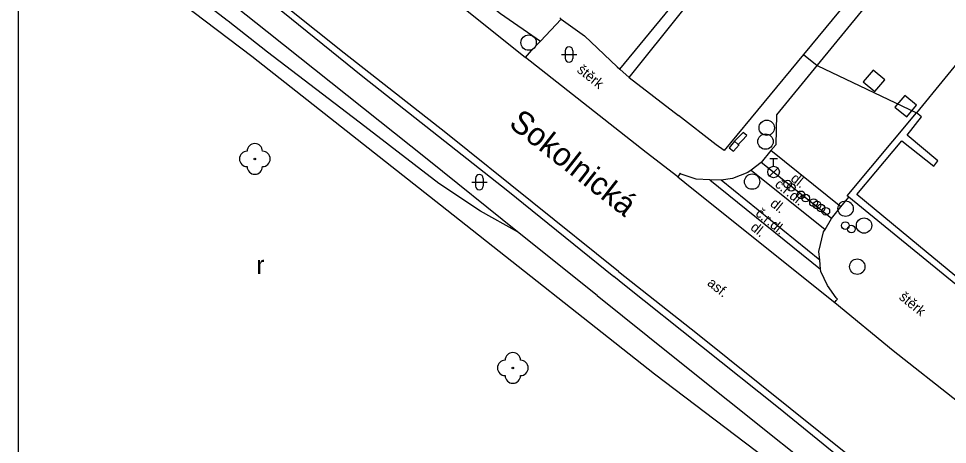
# Model space of a CAD drawing. Extents: x -594386 to -594050, y -1167541 to -1167175.
# Drawn here: x -594386.4 to -594325.8, y -1167256.2 to -1167228.4 of the extents above; entities that cross this region are included whole.
import ezdxf

# ---------------------------------------------------------------- set-up
doc = ezdxf.new("R2010")
doc.units = 0
for name, color, linetype in [('Level 14', 7, 'Continuous'), ('Level 22', 7, 'Continuous'), ('Level 24', 7, 'Continuous'), ('Level 26', 7, 'Continuous'), ('Level 27', 7, 'Continuous'), ('Level 28', 7, 'Continuous'), ('Level 36', 7, 'Continuous'), ('Vrstva 10', 7, 'Continuous'), ('Vrstva 11', 7, 'Continuous'), ('Vrstva 23', 7, 'Continuous'), ('Vrstva 40', 7, 'Continuous'), ('Vrstva 50', 7, 'Continuous'), ('Vrstva 63', 7, 'Continuous'), ('Vrstva 7', 7, 'Continuous'), ('Vrstva 8', 7, 'Continuous')]:
    doc.layers.add(name, color=color, linetype=linetype)

msp = doc.modelspace()

# ---------------------------------------------------------------- linework, layer by layer
at = {"layer": 'Level 14'}
for points in [[(-594372.76, -1167228.57), (-594380.18, -1167222.84), (-594382.36, -1167221.16), (-594386.36, -1167218.111)], [(-594353.85, -1167242.33), (-594359.75, -1167237.6), (-594370.16, -1167229.3), (-594373.63, -1167226.53)], [(-594353.85, -1167242.33), (-594356.26, -1167241), (-594358.99, -1167239.18), (-594363.81, -1167235.48), (-594370.15, -1167230.62), (-594372.71, -1167228.6), (-594372.76, -1167228.57)], [(-594348.66, -1167246.49), (-594353.85, -1167242.33)], [(-594348.66, -1167246.49), (-594343.72, -1167250.47), (-594329.57, -1167261.75), (-594315.59, -1167273.12), (-594302.08, -1167284.23), (-594289.99, -1167294.24), (-594283.19, -1167300.21), (-594279.82, -1167303.19), (-594277.77, -1167305.01), (-594276.73, -1167306.15)]]:
    msp.add_lwpolyline(points, dxfattribs=at)
at = {"layer": 'Level 22'}
for centre in [(-594370.97, -1167237.59), (-594354.16, -1167251.21)]:
    msp.add_circle(centre, 0.05, dxfattribs=at)
for centre, start, end in [((-594371.47, -1167237.59), 90, 270), ((-594370.97, -1167237.09), 0, 180), ((-594370.47, -1167237.59), 270, 90), ((-594370.97, -1167238.09), 180, 0), ((-594354.16, -1167250.71), 0, 180), ((-594354.66, -1167251.21), 90, 270), ((-594353.66, -1167251.21), 270, 90), ((-594354.16, -1167251.71), 180, 0)]:
    msp.add_arc(centre, 0.5, start, end, dxfattribs=at)
at = {"layer": 'Level 24'}
for points in [[(-594339.48, -1167236.64), (-594339.23, -1167236.38), (-594338.92, -1167236.06), (-594339.15, -1167235.87), (-594339.72, -1167236.44)], [(-594339.72, -1167236.44), (-594340.06, -1167236.87), (-594339.78, -1167237.09), (-594339.61, -1167236.89), (-594339.42, -1167236.68), (-594339.48, -1167236.64)], [(-594339.48, -1167236.64), (-594339.72, -1167236.44)]]:
    msp.add_lwpolyline(points, dxfattribs=at)
at = {"layer": 'Level 26'}
for points in [[(-594330.694, -1167231.796), (-594331.334, -1167232.564), (-594330.566, -1167233.204), (-594329.926, -1167232.436)], [(-594328.624, -1167233.446), (-594329.264, -1167234.214), (-594328.496, -1167234.854), (-594327.856, -1167234.086)]]:
    msp.add_lwpolyline(points, close=True, dxfattribs=at)
at = {"layer": 'Level 27'}
for centre in [(-594353.13, -1167230.01), (-594337.62, -1167235.56), (-594337.7, -1167236.46), (-594338.57, -1167239.07), (-594332.48, -1167240.83), (-594331.28, -1167241.93), (-594331.72, -1167244.61)]:
    msp.add_circle(centre, 0.5, dxfattribs=at)
at = {"layer": 'Level 28'}
for p, q in [((-594337.42, -1167237.565), (-594336.92, -1167237.565)), ((-594337.17, -1167238.065), (-594337.17, -1167237.565)), ((-594337.428, -1167238.712), (-594336.898, -1167238.182))]:
    msp.add_line(p, q, dxfattribs=at)
for centre, radius in [((-594337.17, -1167238.44), 0.375), ((-594336.26, -1167239.23), 0.25), ((-594336.02, -1167239.44), 0.25), ((-594335.38, -1167239.93), 0.25), ((-594335.08, -1167240.14), 0.25), ((-594334.57, -1167240.44), 0.25), ((-594334.34, -1167240.59), 0.25), ((-594334.08, -1167240.79), 0.25), ((-594333.77, -1167241), 0.25), ((-594332.5, -1167241.93), 0.25), ((-594332.1, -1167242.16), 0.25)]:
    msp.add_circle(centre, radius, dxfattribs=at)
at = {"layer": 'Level 36'}
for p, q in [((-594350.996, -1167230.786), (-594349.996, -1167230.786)), ((-594350.746, -1167230.536), (-594350.746, -1167231.036)), ((-594350.246, -1167230.536), (-594350.246, -1167231.036)), ((-594356.586, -1167238.856), (-594356.586, -1167239.356)), ((-594356.086, -1167238.856), (-594356.086, -1167239.356)), ((-594356.836, -1167239.106), (-594355.836, -1167239.106))]:
    msp.add_line(p, q, dxfattribs=at)
for centre, start, end in [((-594350.496, -1167230.536), 0, 180), ((-594350.496, -1167231.036), 180, 0), ((-594356.336, -1167238.856), 0, 180), ((-594356.336, -1167239.356), 180, 0)]:
    msp.add_arc(centre, 0.25, start, end, dxfattribs=at)
at = {"layer": 'Vrstva 10'}
for points in [[(-594288.255, -1167175.43), (-594294.11, -1167182.6), (-594312.38, -1167204.76), (-594325.04, -1167220.12), (-594334.343, -1167231.486)], [(-594361.94, -1167224.06), (-594353.34, -1167230.97)], [(-594347.28, -1167244.92), (-594358.53, -1167235.89), (-594365.15, -1167230.7), (-594370.74, -1167226.23)], [(-594324.16, -1167230.06), (-594327.87, -1167234.59)], [(-594343.41, -1167238.75), (-594345.47, -1167237.18), (-594353.34, -1167230.97)], [(-594334.343, -1167231.486), (-594336.99, -1167234.72), (-594337.02, -1167236.66), (-594337.35, -1167237.05)], [(-594332.27, -1167240.07), (-594332.37, -1167239.99), (-594327.87, -1167234.59)], [(-594337.35, -1167237.05), (-594337.98, -1167237.82)], [(-594338.64, -1167238.32), (-594338.86, -1167238.48), (-594339.84, -1167238.86), (-594340.59, -1167238.98)], [(-594337.98, -1167237.82), (-594338.64, -1167238.32)], [(-594341.32, -1167238.95), (-594342.21, -1167238.91), (-594343.19, -1167238.58), (-594343.26, -1167238.52), (-594343.32, -1167238.63), (-594343.41, -1167238.75)], [(-594343.41, -1167238.75), (-594342.49, -1167239.49)], [(-594342.49, -1167239.49), (-594333.19, -1167246.94)], [(-594340.59, -1167238.98), (-594341.32, -1167238.95)], [(-594332.79, -1167240.72), (-594332.27, -1167240.07)], [(-594333.41, -1167241.48), (-594332.79, -1167240.72)], [(-594333.82, -1167242.18), (-594333.41, -1167241.48)], [(-594334.17, -1167244.19), (-594334.22, -1167243.62), (-594333.92, -1167242.34), (-594333.82, -1167242.18)], [(-594334.11, -1167244.77), (-594334.17, -1167244.19)], [(-594347.28, -1167244.92), (-594342.14, -1167248.99), (-594328.08, -1167260.27), (-594314.05, -1167271.66), (-594300.48, -1167282.78), (-594288.32, -1167292.97), (-594276.54, -1167303.08)], [(-594333.19, -1167246.94), (-594333.1, -1167246.82), (-594333, -1167246.72), (-594333.09, -1167246.65), (-594333.65, -1167245.83), (-594334.1, -1167244.92), (-594334.11, -1167244.77)], [(-594333.19, -1167246.94), (-594329.38, -1167250.07), (-594325.19, -1167253.37)]]:
    msp.add_lwpolyline(points, dxfattribs=at)
at = {"layer": 'Vrstva 11'}
for points in [[(-594347.182, -1167231.742), (-594326.73, -1167206.89)], [(-594386.36, -1167219.36), (-594371.16, -1167230.89), (-594358.47, -1167240.9), (-594344.93, -1167251.59)], [(-594361.2, -1167223.15), (-594354.97, -1167228.11), (-594352.36, -1167229.91)], [(-594370.99, -1167226.54), (-594369.15, -1167228.01), (-594363.93, -1167232.21), (-594354.49, -1167239.67), (-594347.58, -1167245.26)], [(-594352.36, -1167229.91), (-594351.01, -1167228.48)], [(-594352.94, -1167230.52), (-594352.36, -1167229.91)], [(-594353.34, -1167230.97), (-594352.94, -1167230.52)], [(-594335.22, -1167230.78), (-594334.34, -1167231.49)], [(-594334.34, -1167231.49), (-594327.87, -1167234.59)], [(-594332.79, -1167240.72), (-594337.35, -1167237.05)], [(-594338.64, -1167238.32), (-594333.82, -1167242.18)], [(-594333.41, -1167241.48), (-594337.98, -1167237.82)], [(-594341.32, -1167238.95), (-594334.11, -1167244.77)], [(-594334.17, -1167244.19), (-594340.59, -1167238.98)], [(-594276.49, -1167304.67), (-594278.35, -1167302.91), (-594288.79, -1167293.6), (-594300.84, -1167283.3), (-594312.94, -1167273.4), (-594318.93, -1167268.41), (-594326.02, -1167262.62), (-594336.86, -1167253.82), (-594346.88, -1167245.82), (-594347.58, -1167245.26)]]:
    msp.add_lwpolyline(points, dxfattribs=at)
at = {"layer": 'Vrstva 23'}
msp.add_lwpolyline([(-594344.93, -1167251.59), (-594330.46, -1167262.57), (-594316.33, -1167274.13), (-594302.78, -1167285.35)], dxfattribs=at)
at = {"layer": 'Vrstva 63'}
msp.add_lwpolyline([(-594386.36, -1167175.43), (-594049.75, -1167175.43), (-594049.75, -1167540.79), (-594386.36, -1167540.79)], close=True, dxfattribs=at)
at = {"layer": 'Vrstva 7'}
for points in [[(-594293.29, -1167179.81), (-594294.47, -1167181.2), (-594313.23, -1167204.15), (-594335.22, -1167230.78)], [(-594346.59, -1167232.28), (-594343.09, -1167227.92)], [(-594351.108, -1167228.403), (-594351.01, -1167228.48)], [(-594351.01, -1167228.48), (-594349.5, -1167229.57)], [(-594335.22, -1167230.78), (-594340.39, -1167237.04), (-594340.91, -1167236.68)], [(-594347.36, -1167231.58), (-594347.182, -1167231.742)], [(-594347.182, -1167231.742), (-594346.59, -1167232.28)], [(-594346.59, -1167232.28), (-594343.36, -1167234.76)], [(-594327.54, -1167234.85), (-594327.87, -1167234.59)], [(-594331.76, -1167239.9), (-594330.51, -1167238.42), (-594328.81, -1167236.41), (-594326.74, -1167238.05), (-594326.48, -1167237.72), (-594328.48, -1167236.05), (-594327.54, -1167234.85)], [(-594321.04, -1167248.75), (-594321.29, -1167249.06), (-594332.27, -1167240.07)], [(-594327.73, -1167243.23), (-594331.76, -1167239.9)], [(-594321.62, -1167248.27), (-594327.73, -1167243.23)]]:
    msp.add_lwpolyline(points, dxfattribs=at)
at = {"layer": 'Vrstva 8'}
for points in [[(-594349.5, -1167229.57), (-594347.36, -1167231.58)], [(-594340.91, -1167236.68), (-594343.36, -1167234.76)]]:
    msp.add_lwpolyline(points, dxfattribs=at)

# ---------------------------------------------------------------- texts
at = {"layer": 'Level 36'}
msp.add_text('r', height=1.2, dxfattribs=at).set_placement((-594370.873, -1167245.097))
at = {"layer": 'Vrstva 40'}
for s, rotation, p in [('štěrk', 321.37, (-594350.03, -1167231.88)), ('č.r.dl.', 321.05899, (-594337.14, -1167239.34)), ('dl.', 321.05899, (-594336.11, -1167238.96)), ('dl.', 321.05899, (-594337.45, -1167240.6)), ('č.r.dl.', 321.05899, (-594338.4, -1167241.23)), ('dl.', 321.05899, (-594338.73, -1167242.15)), ('asf.', 321, (-594341.54, -1167245.77)), ('štěrk', 320.59, (-594329.05, -1167246.68))]:
    msp.add_text(s, height=0.65, rotation=rotation, dxfattribs=at).set_placement(p)
at = {"layer": 'Vrstva 50'}
msp.add_text('Sokolnická', height=1.5, rotation=321.87284, dxfattribs=at).set_placement((-594354.492, -1167235.424))

doc.saveas('drawing.dxf')
